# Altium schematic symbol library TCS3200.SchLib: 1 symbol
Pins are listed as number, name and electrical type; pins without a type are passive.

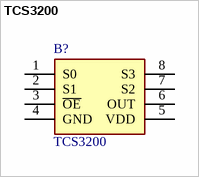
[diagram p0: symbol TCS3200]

## TCS3200
designator B?
High-Resolution Conversion of Light Intensity to Frequency  Programmable Color and Full-Scale Output Frequency  Communicates Directly With a Microcontroller  Single-Supply Operation (2.7 V to 5.5 V)  Power Down Feature  Nonlinearity Error Typically 0.2% at 50 kHz; Manufacturer_Name: ams; Geometry.Height: 1.75mm
footprint SOIC127P600X175-8N
pins: 1 S0, 2 S1, 3 ~{OE}, 4 GND, 5 VDD, 6 OUT, 7 S2, 8 S3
